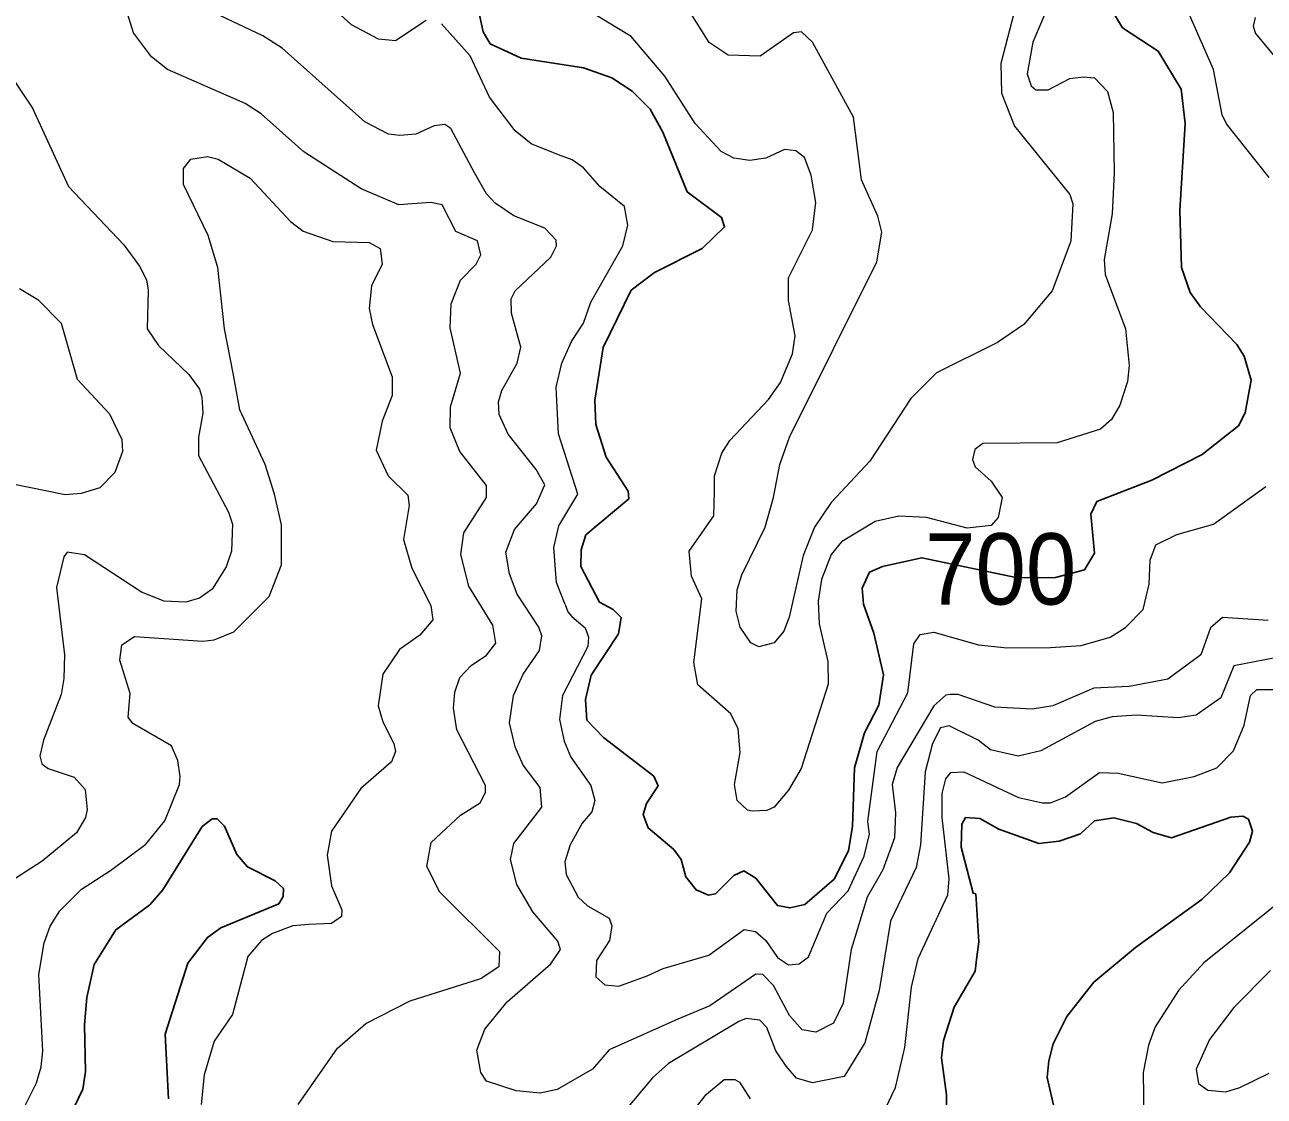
# Model space of a CAD drawing. Extents: x 294.2 to 320.3, y 7482.7 to 7510.7.
# Drawn here: x 303.181 to 304.57, y 7484.042 to 7485.244 of the extents above; entities that cross this region are included whole.
import ezdxf
from ezdxf.enums import TextEntityAlignment as Align

# ---------------------------------------------------------------- set-up
doc = ezdxf.new("R2010")
doc.units = 0
doc.header["$LTSCALE"] = 0.032
doc.layers.add('1', color=7, linetype='Continuous', lineweight=25)
doc.layers.add('2', color=7, linetype='Continuous', lineweight=13)
doc.layers.add('61', color=7, linetype='Continuous')

msp = doc.modelspace()

# ---------------------------------------------------------------- linework, layer by layer
at = {"layer": '1'}
for points in [[(303.6821, 7485.2947), (303.6948, 7485.236), (303.7025, 7485.2226), (303.7376, 7485.2066), (303.8073, 7485.1957), (303.8389, 7485.1844), (303.8617, 7485.1693), (303.8822, 7485.1494), (303.8961, 7485.1236), (303.9235, 7485.0564), (303.9618, 7485.0279), (303.9654, 7485.0171), (303.9404, 7484.9929), (303.8869, 7484.966)], [(303.8575, 7484.7207), (303.858, 7484.7121), (303.8098, 7484.6718), (303.8048, 7484.6551), (303.8043, 7484.6362), (303.8251, 7484.5964), (303.8406, 7484.5883), (303.8495, 7484.5792), (303.8467, 7484.5609), (303.816, 7484.5147), (303.8094, 7484.4873), (303.811, 7484.4642), (303.8296, 7484.4448), (303.8861, 7484.4012), (303.8911, 7484.3905), (303.8778, 7484.3706), (303.8742, 7484.3582), (303.8797, 7484.3432), (303.9086, 7484.319), (303.9169, 7484.3077), (303.9219, 7484.2883), (303.9336, 7484.2738), (303.9475, 7484.2679), (303.9551, 7484.2693), (303.9759, 7484.2897), (303.987, 7484.295), (304.0003, 7484.287), (304.0247, 7484.2563), (304.0386, 7484.2536), (304.0555, 7484.2574), (304.0882, 7484.2859), (304.1043, 7484.3177), (304.109, 7484.3451), (304.1112, 7484.4107), (304.1223, 7484.4498), (304.1384, 7484.481), (304.1434, 7484.5148), (304.1328, 7484.5617), (304.1211, 7484.594), (304.1195, 7484.6122), (304.1278, 7484.63), (304.1423, 7484.6364), (304.1865, 7484.6461), (304.2938, 7484.6236), (304.3365, 7484.6241), (304.3689, 7484.6327), (304.38, 7484.6515), (304.3761, 7484.6951), (304.3828, 7484.7091), (304.4443, 7484.7333), (304.5008, 7484.7619), (304.5413, 7484.7942), (304.5491, 7484.8087), (304.5555, 7484.8453), (304.5479, 7484.8721), (304.5395, 7484.8855), (304.4987, 7484.9276), (304.4872, 7484.9436), (304.4776, 7484.9717), (304.4757, 7485.0356), (304.4816, 7485.1331), (304.4772, 7485.1718), (304.4514, 7485.2143), (304.4115, 7485.2406), (304.4015, 7485.2573)], [(303.8869, 7484.966), (303.8608, 7484.9461), (303.8295, 7484.8821), (303.8201, 7484.8229), (303.8212, 7484.7955), (303.8328, 7484.7589), (303.8575, 7484.7207)], [(303.2313, 7484.0191), (303.246, 7484.0504), (303.2492, 7484.0702), (303.2479, 7484.1225), (303.2505, 7484.1532), (303.2587, 7484.1902), (303.283, 7484.2291), (303.3213, 7484.257), (303.3357, 7484.2737), (303.38, 7484.3447), (303.3911, 7484.3533), (303.3967, 7484.3533), (303.405, 7484.3452), (303.4189, 7484.3134), (303.4305, 7484.2995), (303.4616, 7484.2839), (303.471, 7484.2753), (303.4707, 7484.2662), (303.4657, 7484.2581), (303.4008, 7484.2312), (303.3858, 7484.2205), (303.3637, 7484.1914), (303.3384, 7484.1118), (303.3421, 7484.0393)], [(304.2139, 7484.0083), (304.214, 7484.0439), (304.2084, 7484.0853), (304.2107, 7484.1047), (304.2226, 7484.1423), (304.2464, 7484.1827), (304.2481, 7484.1988), (304.2503, 7484.2155), (304.2469, 7484.2692), (304.2439, 7484.27), (304.2305, 7484.3217), (304.2312, 7484.3473), (304.2356, 7484.3549), (304.2516, 7484.3536), (304.2727, 7484.3418), (304.3176, 7484.3257), (304.3404, 7484.3284), (304.3645, 7484.3365), (304.3801, 7484.351), (304.4017, 7484.3547), (304.4272, 7484.3483), (304.4458, 7484.3381), (304.4664, 7484.3321), (304.5329, 7484.3553), (304.5465, 7484.3564), (304.5526, 7484.3531), (304.557, 7484.3397), (304.5537, 7484.3273), (304.5315, 7484.2929), (304.5004, 7484.2629), (304.426, 7484.2091), (304.3792, 7484.1703), (304.3492, 7484.1316), (304.3337, 7484.101), (304.3287, 7484.0822), (304.327, 7484.0633), (304.3351, 7484.0273)]]:
    msp.add_lwpolyline(points, dxfattribs=at)
at = {"layer": '2'}
for points in [[(303.6629, 7484.4954), (303.6687, 7484.512), (303.6814, 7484.5254), (303.6986, 7484.5369), (303.7089, 7484.5503), (303.7057, 7484.5707), (303.6789, 7484.6142), (303.6699, 7484.6499), (303.6731, 7484.6742), (303.6986, 7484.7138), (303.6986, 7484.7271), (303.6687, 7484.7654), (303.6578, 7484.7917), (303.6584, 7484.8153), (303.6693, 7484.853), (303.6578, 7484.904), (303.6591, 7484.9308), (303.6693, 7484.9576), (303.6871, 7484.9755), (303.6923, 7484.9858), (303.6885, 7485.0017), (303.6642, 7485.0119), (303.6489, 7485.0419), (303.6361, 7485.0444), (303.6004, 7485.0419), (303.5582, 7485.0598), (303.4937, 7485.1013), (303.4459, 7485.1441), (303.428, 7485.1556), (303.3411, 7485.1939), (303.3232, 7485.2079), (303.3028, 7485.2348), (303.2818, 7485.3024)], [(303.631, 7485.2488), (303.5965, 7485.2258), (303.5774, 7485.2277), (303.5474, 7485.2437), (303.4994, 7485.2877)], [(304.2924, 7485.2667), (304.2752, 7485.2003), (304.2758, 7485.1671), (304.2905, 7485.1301), (304.3524, 7485.0534), (304.3557, 7485.0432), (304.3537, 7485.0011), (304.3327, 7484.9455), (304.3008, 7484.9078), (304.2714, 7484.8874), (304.2031, 7484.8536), (304.1743, 7484.8248), (304.1284, 7484.7546), (304.085, 7484.708), (304.0664, 7484.6806), (304.0536, 7484.6486), (304.0377, 7484.5797), (304.0319, 7484.5639), (304.0211, 7484.5509), (304.0039, 7484.5464), (303.9949, 7484.5509), (303.9828, 7484.5682), (303.9783, 7484.5861), (303.9795, 7484.6103), (303.9847, 7484.6269), (304.0109, 7484.6806), (304.0204, 7484.7138), (304.0275, 7484.7508), (304.0383, 7484.7814), (304.136, 7484.9781), (304.1417, 7485.0113), (304.1373, 7485.0292), (304.1188, 7485.07), (304.1098, 7485.1403), (304.0639, 7485.2245), (304.0518, 7485.236), (304.0428, 7485.2348), (304.0052, 7485.2086), (303.9694, 7485.2099), (303.9483, 7485.2239), (303.926, 7485.259)], [(304.3327, 7485.2756), (304.311, 7485.2245), (304.3046, 7485.1888), (304.309, 7485.1753), (304.3142, 7485.1709), (304.3282, 7485.1709), (304.3525, 7485.1836), (304.3678, 7485.1856), (304.3799, 7485.1843), (304.3946, 7485.169), (304.401, 7485.1454), (304.4022, 7485.0777), (304.3997, 7485.0317), (304.3908, 7484.9806), (304.392, 7484.964), (304.415, 7484.9028), (304.4188, 7484.8619), (304.417, 7484.844), (304.4086, 7484.8172), (304.3991, 7484.8012), (304.3869, 7484.7903), (304.3384, 7484.775), (304.2548, 7484.7744), (304.2458, 7484.7674), (304.2433, 7484.7565), (304.2465, 7484.7482), (304.2643, 7484.7322), (304.2765, 7484.7137), (304.272, 7484.6914), (304.2643, 7484.6825), (304.2375, 7484.6792)], [(303.9132, 7484.1289), (303.8359, 7484.0944), (303.8174, 7484.0727), (303.7779, 7484.0497), (303.7587, 7484.0459), (303.7319, 7484.0484), (303.6987, 7484.0593), (303.6923, 7484.0689), (303.6878, 7484.0938), (303.6968, 7484.1174), (303.7216, 7484.1481), (303.7708, 7484.1908), (303.7816, 7484.2068), (303.7785, 7484.2164), (303.7504, 7484.249), (303.7325, 7484.2796), (303.7255, 7484.3077), (303.7293, 7484.3256), (303.7606, 7484.3664), (303.7587, 7484.3887), (303.7395, 7484.4136), (303.7306, 7484.4341), (303.7242, 7484.4609), (303.7287, 7484.4916), (303.7395, 7484.5158), (303.7581, 7484.542), (303.7606, 7484.5586), (303.7574, 7484.5682), (303.7331, 7484.6052), (303.7242, 7484.6282), (303.7204, 7484.6524), (303.73, 7484.678), (303.7548, 7484.7067), (303.7638, 7484.7278), (303.7542, 7484.745), (303.7229, 7484.7846), (303.7127, 7484.807), (303.7121, 7484.821), (303.7159, 7484.8338), (303.7331, 7484.8644), (303.737, 7484.8823), (303.7267, 7484.9206), (303.7261, 7484.9366), (303.7306, 7484.9455), (303.7708, 7484.9832), (303.7772, 7484.9959), (303.7765, 7485.0023), (303.7638, 7485.0157), (303.7293, 7485.0298), (303.7083, 7485.0438), (303.6986, 7485.0541), (303.6853, 7485.0777), (303.6585, 7485.1275), (303.652, 7485.132), (303.6399, 7485.1307), (303.6195, 7485.1211), (303.6016, 7485.1198), (303.5888, 7485.1211), (303.5621, 7485.1351), (303.4694, 7485.2175), (303.4477, 7485.2316), (303.3935, 7485.2571)], [(304.0741, 7484.6218), (304.0702, 7484.5976), (304.0715, 7484.572), (304.0811, 7484.5299), (304.0817, 7484.5043), (304.0511, 7484.4098), (304.037, 7484.3856), (304.0211, 7484.3664), (304.0128, 7484.3626), (303.9962, 7484.362), (303.9911, 7484.3632), (303.9796, 7484.374), (303.9764, 7484.392), (303.9828, 7484.4277), (303.9808, 7484.4545), (303.9726, 7484.4711), (303.9355, 7484.5037), (303.931, 7484.5286), (303.94, 7484.6001), (303.9285, 7484.6257), (303.9259, 7484.6537), (303.9534, 7484.6933), (303.954, 7484.7201), (303.954, 7484.738), (303.9624, 7484.7636), (303.9713, 7484.7776), (304.0147, 7484.8236), (304.0281, 7484.8427), (304.0415, 7484.8747), (304.0447, 7484.8951), (304.037, 7484.9347), (304.037, 7484.9602), (304.0639, 7485.0138), (304.0677, 7485.0445), (304.0626, 7485.0751), (304.0549, 7485.0949), (304.0453, 7485.1026), (304.0326, 7485.1039), (304.0115, 7485.0943), (303.9937, 7485.0917), (303.9758, 7485.0943), (303.9617, 7485.1019), (303.9323, 7485.1332), (303.8985, 7485.1862), (303.8608, 7485.2309), (303.8078, 7485.2628)], [(304.5759, 7485.0726), (304.5281, 7485.1326), (304.523, 7485.1428), (304.5133, 7485.1939), (304.4865, 7485.2552)], [(304.56, 7485.252), (304.558, 7485.2424), (304.5606, 7485.2341), (304.5919, 7485.1965)], [(303.7868, 7484.5937), (303.7772, 7484.6186), (303.774, 7484.6576), (303.7798, 7484.6818), (303.8008, 7484.7176), (303.7791, 7484.7853), (303.7765, 7484.8376), (303.7829, 7484.8644), (303.7938, 7484.8887), (303.8072, 7484.9091), (303.8155, 7484.9328), (303.8513, 7484.996), (303.857, 7485.019), (303.8532, 7485.04), (303.8257, 7485.0624), (303.8072, 7485.0834), (303.7945, 7485.0924), (303.7791, 7485.0981), (303.7485, 7485.1103), (303.7306, 7485.1249), (303.7019, 7485.1626), (303.6802, 7485.2092), (303.6482, 7485.2449)], [(303.1598, 7485.1952), (303.1898, 7485.1505), (303.23, 7485.0624), (303.292, 7484.9972), (303.3098, 7484.973), (303.3175, 7484.9577), (303.3194, 7484.9462), (303.3181, 7484.9028), (303.3309, 7484.8842), (303.3648, 7484.8517), (303.3769, 7484.8351), (303.3794, 7484.8261), (303.3807, 7484.8083), (303.3756, 7484.7814), (303.3756, 7484.761), (303.4095, 7484.6972), (303.4139, 7484.6837), (303.4126, 7484.6537), (303.4069, 7484.6359), (303.3909, 7484.611), (303.3769, 7484.6007), (303.3616, 7484.5962), (303.3373, 7484.5975), (303.3118, 7484.6077), (303.2479, 7484.6493), (303.2287, 7484.6524), (303.2249, 7484.6474), (303.2166, 7484.6129), (303.2256, 7484.5375), (303.2249, 7484.5107), (303.2217, 7484.4929), (303.2019, 7484.4418), (303.1981, 7484.4239), (303.2, 7484.4149), (303.2071, 7484.4098), (303.2364, 7484.4003), (303.2486, 7484.3862), (303.2511, 7484.3639), (303.2492, 7484.3549), (303.239, 7484.3377), (303.2007, 7484.3058), (303.1387, 7484.2662)], [(303.3973, 7484.9717), (303.3865, 7485.0075), (303.359, 7485.0649), (303.359, 7485.0828), (303.3673, 7485.093), (303.3858, 7485.0962), (303.3979, 7485.093)], [(303.3979, 7485.093), (303.4337, 7485.0719), (303.479, 7485.0234), (303.4931, 7485.0125), (303.5263, 7485.001), (303.5672, 7484.9998), (303.5793, 7484.9928), (303.5818, 7484.9755), (303.5697, 7484.9513), (303.5671, 7484.9257), (303.5709, 7484.9079), (303.5927, 7484.8491), (303.5927, 7484.828), (303.5818, 7484.7993), (303.5748, 7484.7667), (303.5882, 7484.738), (303.6105, 7484.7163), (303.6118, 7484.7048), (303.6054, 7484.6665), (303.615, 7484.6346), (303.6361, 7484.5925), (303.6386, 7484.5765), (303.624, 7484.5592), (303.601, 7484.5433), (303.5824, 7484.5158), (303.5773, 7484.4801), (303.5824, 7484.4622), (303.5946, 7484.4379), (303.5965, 7484.429), (303.592, 7484.4175), (303.5576, 7484.3875), (303.525, 7484.3396), (303.5199, 7484.3128), (303.525, 7484.2783), (303.5365, 7484.2515), (303.5359, 7484.2438), (303.525, 7484.2361), (303.4995, 7484.2349), (303.4816, 7484.2336), (303.4586, 7484.2247), (303.4465, 7484.217), (303.4312, 7484.1991), (303.4139, 7484.134), (303.3935, 7484.104), (303.382, 7484.0663), (303.3788, 7484.0331)], [(303.1809, 7484.0306), (303.1942, 7484.0574), (303.1994, 7484.0753), (303.2013, 7484.0932), (303.1968, 7484.1787), (303.2026, 7484.2145), (303.2096, 7484.233), (303.2205, 7484.2502), (303.2447, 7484.2744), (303.2773, 7484.2956), (303.3168, 7484.3249), (303.3379, 7484.3511), (303.3545, 7484.392), (303.3551, 7484.4009), (303.3526, 7484.4188), (303.3456, 7484.4354), (303.3022, 7484.4603), (303.2971, 7484.4673), (303.299, 7484.4941), (303.2875, 7484.5312), (303.29, 7484.5484), (303.3041, 7484.5579), (303.3807, 7484.5528), (303.3935, 7484.5541), (303.4152, 7484.563), (303.4548, 7484.6027), (303.4688, 7484.6384), (303.4688, 7484.6831), (303.4611, 7484.7176), (303.4503, 7484.7508), (303.4222, 7484.8121), (303.4146, 7484.853), (303.4049, 7484.9028), (303.3973, 7484.9717)], [(303.1751, 7484.9481), (303.1956, 7484.9359), (303.2217, 7484.9091), (303.2396, 7484.8466), (303.276, 7484.8076), (303.29, 7484.7789), (303.2907, 7484.7655), (303.2818, 7484.7419), (303.2652, 7484.7246), (303.2441, 7484.7182), (303.2262, 7484.7169), (303.1656, 7484.729)], [(303.7868, 7484.5937), (303.7897, 7484.5855), (303.7944, 7484.5803), (303.8091, 7484.5675), (303.813, 7484.5573), (303.8123, 7484.5465), (303.7836, 7484.4916), (303.7804, 7484.4648), (303.7855, 7484.4405), (303.7931, 7484.4226), (303.8155, 7484.3907), (303.82, 7484.3741), (303.8168, 7484.3613), (303.8059, 7484.3485), (303.7925, 7484.3243), (303.7862, 7484.3051), (303.788, 7484.2911), (303.8015, 7484.2655), (303.8117, 7484.2559), (303.8359, 7484.2419), (303.8391, 7484.2336), (303.8366, 7484.217), (303.8219, 7484.1947), (303.8212, 7484.1762), (303.8314, 7484.1672), (303.8468, 7484.1659), (303.8787, 7484.1774), (303.8966, 7484.1857), (303.9477, 7484.2004), (303.9873, 7484.2292), (304, 7484.2272), (304.0115, 7484.217), (304.0249, 7484.1978), (304.0371, 7484.1896), (304.0492, 7484.1908), (304.0594, 7484.1985), (304.0799, 7484.2477), (304.1041, 7484.2726), (304.122, 7484.3115), (304.1277, 7484.3363), (304.126, 7484.3503), (304.1363, 7484.4291), (304.1707, 7484.4948), (304.1777, 7484.5496), (304.1846, 7484.5601), (304.2001, 7484.5629), (304.25, 7484.5484), (304.2821, 7484.5451), (304.3309, 7484.5454), (304.3653, 7484.5476), (304.3978, 7484.5573), (304.415, 7484.5681), (304.4348, 7484.588), (304.4412, 7484.6167), (304.4425, 7484.6435), (304.4489, 7484.6608), (304.4725, 7484.6723), (304.5134, 7484.6837), (304.5721, 7484.7259)], [(304.2375, 7484.6792), (304.1916, 7484.6914), (304.1609, 7484.6927), (304.1341, 7484.6869), (304.0964, 7484.6639), (304.085, 7484.6499), (304.0741, 7484.6218)], [(304.5747, 7484.5758), (304.5236, 7484.579), (304.5102, 7484.5675), (304.4993, 7484.5375), (304.4623, 7484.5101), (304.4189, 7484.5017), (304.3793, 7484.4999), (304.3333, 7484.48), (304.3103, 7484.4762), (304.2682, 7484.4788), (304.2273, 7484.4928), (304.2184, 7484.4928), (304.2133, 7484.4922), (304.1999, 7484.4801), (304.159, 7484.4111), (304.1532, 7484.392), (304.1571, 7484.36), (304.1558, 7484.332), (304.143, 7484.2962), (304.1251, 7484.2656), (304.1073, 7484.2068), (304.0983, 7484.1468), (304.0875, 7484.1244), (304.0677, 7484.1142), (304.0524, 7484.1168)], [(304.6174, 7484.5407), (304.5363, 7484.5248), (304.5217, 7484.489), (304.4942, 7484.4698), (304.4738, 7484.4667), (304.4266, 7484.4698), (304.3997, 7484.4679), (304.381, 7484.4625), (304.32, 7484.4297), (304.2945, 7484.4238), (304.2634, 7484.4308), (304.2495, 7484.4416), (304.2173, 7484.4577), (304.2074, 7484.4555), (304.1986, 7484.4379), (304.1903, 7484.406), (304.1852, 7484.3243), (304.1801, 7484.2988), (304.1514, 7484.2387), (304.1386, 7484.1608), (304.1226, 7484.1021), (304.0996, 7484.0644), (304.0639, 7484.0574), (304.046, 7484.0625), (304.0345, 7484.0759), (304.023, 7484.0932), (304.0128, 7484.1193), (304.0051, 7484.1276), (303.9898, 7484.1296), (303.9815, 7484.1263), (303.9024, 7484.0791), (303.8845, 7484.0631), (303.8538, 7484.0261)], [(303.6693, 7484.3575), (303.6916, 7484.3715), (303.6974, 7484.383), (303.6974, 7484.3907), (303.6654, 7484.4533), (303.6616, 7484.4775), (303.6629, 7484.4954)], [(304.4559, 7484.3939), (304.4917, 7484.4009), (304.5172, 7484.4105), (304.5357, 7484.4296), (304.5478, 7484.4584), (304.5549, 7484.4916), (304.5619, 7484.4986), (304.6028, 7484.4986)], [(304.1463, 7484.0293), (304.1571, 7484.0523), (304.1673, 7484.097), (304.1749, 7484.1647), (304.1826, 7484.1966), (304.2158, 7484.2681), (304.2171, 7484.286), (304.2094, 7484.3549), (304.2094, 7484.3818), (304.2133, 7484.3984), (304.219, 7484.4053), (304.2337, 7484.406), (304.295, 7484.3773)], [(304.295, 7484.3773), (304.3218, 7484.3715), (304.3308, 7484.3715), (304.3474, 7484.3779), (304.3856, 7484.4054), (304.4067, 7484.4047), (304.4559, 7484.3939)], [(303.4873, 7484.0331), (303.5314, 7484.0964), (303.5633, 7484.1238), (303.6131, 7484.1493), (303.6923, 7484.1742), (303.7127, 7484.1883), (303.7134, 7484.2042), (303.6463, 7484.2713), (303.6316, 7484.3), (303.6367, 7484.3268), (303.6693, 7484.3575)], [(304.6449, 7484.3064), (304.5025, 7484.1921), (304.4744, 7484.1608), (304.4482, 7484.12), (304.4406, 7484.0996), (304.4348, 7484.0689), (304.4354, 7484.0178)], [(304.5772, 7484.1832), (304.5363, 7484.1417), (304.5089, 7484.1059), (304.4942, 7484.0727), (304.4968, 7484.0567), (304.507, 7484.0491), (304.5274, 7484.0471), (304.5428, 7484.0523), (304.576, 7484.0683)], [(304.0524, 7484.1168), (304.0383, 7484.1328), (304.0204, 7484.1666), (304.0083, 7484.1787), (304.0006, 7484.1794), (303.949, 7484.1436), (303.9132, 7484.1289)], [(303.9017, 7483.9897), (303.9451, 7484.0446), (303.9649, 7484.0612), (303.9771, 7484.0612), (303.9822, 7484.058), (303.9943, 7484.0395)]]:
    msp.add_lwpolyline(points, dxfattribs=at)

# ---------------------------------------------------------------- texts
at = {"layer": '61', "width": 0.95}
msp.add_text('700', height=0.08, dxfattribs=at).set_placement((304.2749, 7484.5937), align=Align.CENTER)

doc.saveas('drawing.dxf')
